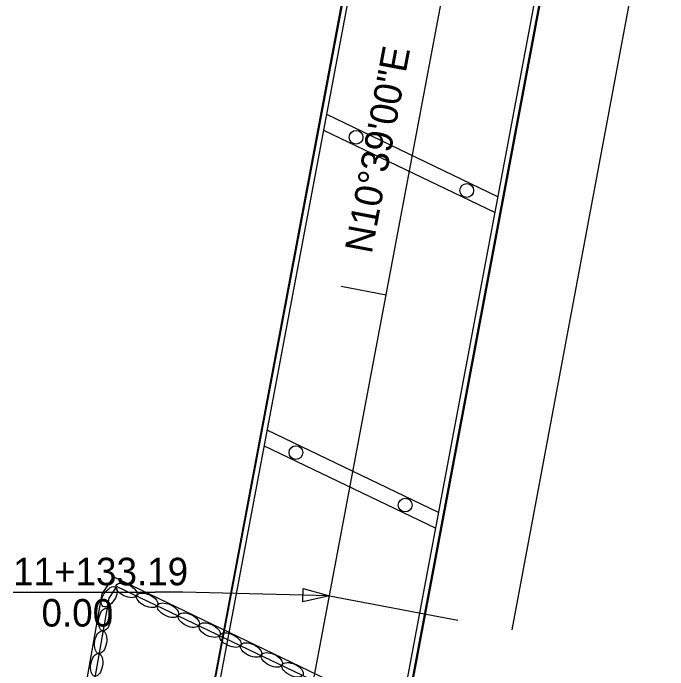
# Model space of a CAD drawing. Extents: x 674098 to 689971, y 764717 to 781049.
# Drawn here: x 688601.9 to 688744.6, y 766201 to 766344.1 of the extents above; entities that cross this region are included whole.
import ezdxf

# ---------------------------------------------------------------- set-up
doc = ezdxf.new("R2010")
doc.units = 0
for name, color, linetype in [('BRIDGE', 7, 'Continuous'), ('Level 1', 7, 'Continuous'), ('R_Horz Alg', 7, 'Continuous'), ('R_Horz Alg Annot', 7, 'Continuous'), ('R_Horz Alg Station', 7, 'Continuous'), ('R_No Plot', 7, 'Continuous'), ('R_Proposed Const Limits', 7, 'Continuous'), ('R_Proposed Riprap', 7, 'Continuous')]:
    doc.layers.add(name, color=color, linetype=linetype)

msp = doc.modelspace()

# ---------------------------------------------------------------- linework, layer by layer
at = {"layer": 'BRIDGE'}
for p, q in [((688645.49, 766197.09), (688691.88, 766443.79)), ((688645.65, 766197.06), (688692.05, 766443.76)), ((688646.72, 766196.86), (688693.11, 766443.56)), ((688684.05, 766178.93), (688730.44, 766425.64)), ((688685.11, 766178.73), (688731.51, 766425.44)), ((688731.67, 766425.41), (688685.28, 766178.7))]:
    msp.add_line(p, q, dxfattribs=at)
at = {"layer": 'Level 1'}
for p, q in [((688707.58, 766304.07), (688670.25, 766322)), ((688706.93, 766300.63), (688669.6, 766318.56)), ((688694.64, 766235.28), (688657.31, 766253.2)), ((688694, 766231.84), (688656.67, 766249.76))]:
    msp.add_line(p, q, dxfattribs=at)
for centre in [(688676.65, 766317.05), (688700.77, 766305.46), (688663.56, 766248.33), (688687.37, 766236.89)]:
    msp.add_circle(centre, 1.5, dxfattribs=at)
at = {"layer": 'R_Horz Alg'}
msp.add_line((688649.13, 766101.47), (688735.51, 766560.83), dxfattribs=at)
msp.add_line((688649.13, 766101.47), (688735.51, 766560.83), dxfattribs=at)
at = {"layer": 'R_Horz Alg Station'}
msp.add_lwpolyline([(688673.39, 766284.6), (688683.22, 766282.75)], dxfattribs=at)
at = {"layer": 'R_No Plot'}
for p, q in [((688744.63, 766391.33), (688710.59, 766209.69)), ((688601.9, 766217.92), (688632.86, 766217.92)), ((688670.88, 766217.1), (688698.81, 766211.84))]:
    msp.add_line(p, q, dxfattribs=at)
msp.add_lwpolyline([(688670.88, 766217.1), (688665.02, 766215.79), (688665.09, 766218.7)], close=True, dxfattribs=at)
msp.add_lwpolyline([(688670.88, 766217.1), (688638.86, 766217.92), (688632.86, 766217.92)], dxfattribs=at)
at = {"layer": 'R_Proposed Const Limits'}
msp.add_lwpolyline([(688612.56, 766151.99), (688614.76, 766180.47), (688621.32, 766217.54), (688623.84, 766221.24), (688687.58, 766190.63)], dxfattribs=at)
at = {"layer": 'R_Proposed Riprap'}
msp.add_lwpolyline([(688645.25, 766197.58), (688640.33, 766198.51), (688635.71, 766173.92), (688615.91, 766177.52), (688622.83, 766216.61), (688624.5, 766219.15), (688721.7, 766172.67), (688738.5, 766169.44), (688734.47, 766143.07), (688685.96, 766152.66), (688690.41, 766176.89), (688685.52, 766178.22)], dxfattribs=at)
for centre, major_axis in [((688626.6, 766218.31), (-2.26, 1.08)), ((688622.86, 766216.92), (-1.37, -2.09)), ((688631.13, 766216.14), (-2.26, 1.08)), ((688635.66, 766213.98), (-2.26, 1.08)), ((688621.86, 766211.96), (-0.44, -2.46)), ((688640.19, 766211.81), (-2.26, 1.08)), ((688644.72, 766209.65), (-2.26, 1.08)), ((688620.98, 766207.02), (-0.44, -2.46)), ((688649.25, 766207.48), (-2.26, 1.08)), ((688653.77, 766205.31), (-2.26, 1.08)), ((688620.11, 766202.07), (-0.44, -2.46)), ((688658.3, 766203.15), (-2.26, 1.08)), ((688662.83, 766200.98), (-2.26, 1.08))]:
    msp.add_ellipse(centre, major_axis=major_axis, ratio=0.517889, dxfattribs=at)

# ---------------------------------------------------------------- texts
at = {"layer": 'R_Horz Alg Annot'}
msp.add_text('N10%%d39\'00"E', height=6, rotation=79.35, dxfattribs=at).set_placement((688680.06, 766291.5))
at = {"layer": 'R_No Plot'}
for s, p in [('11+133.19', (688601.9, 766219.42)), ('0.00', (688608.09, 766210.42))]:
    msp.add_text(s, height=6, dxfattribs=at).set_placement(p)

doc.saveas('drawing.dxf')
